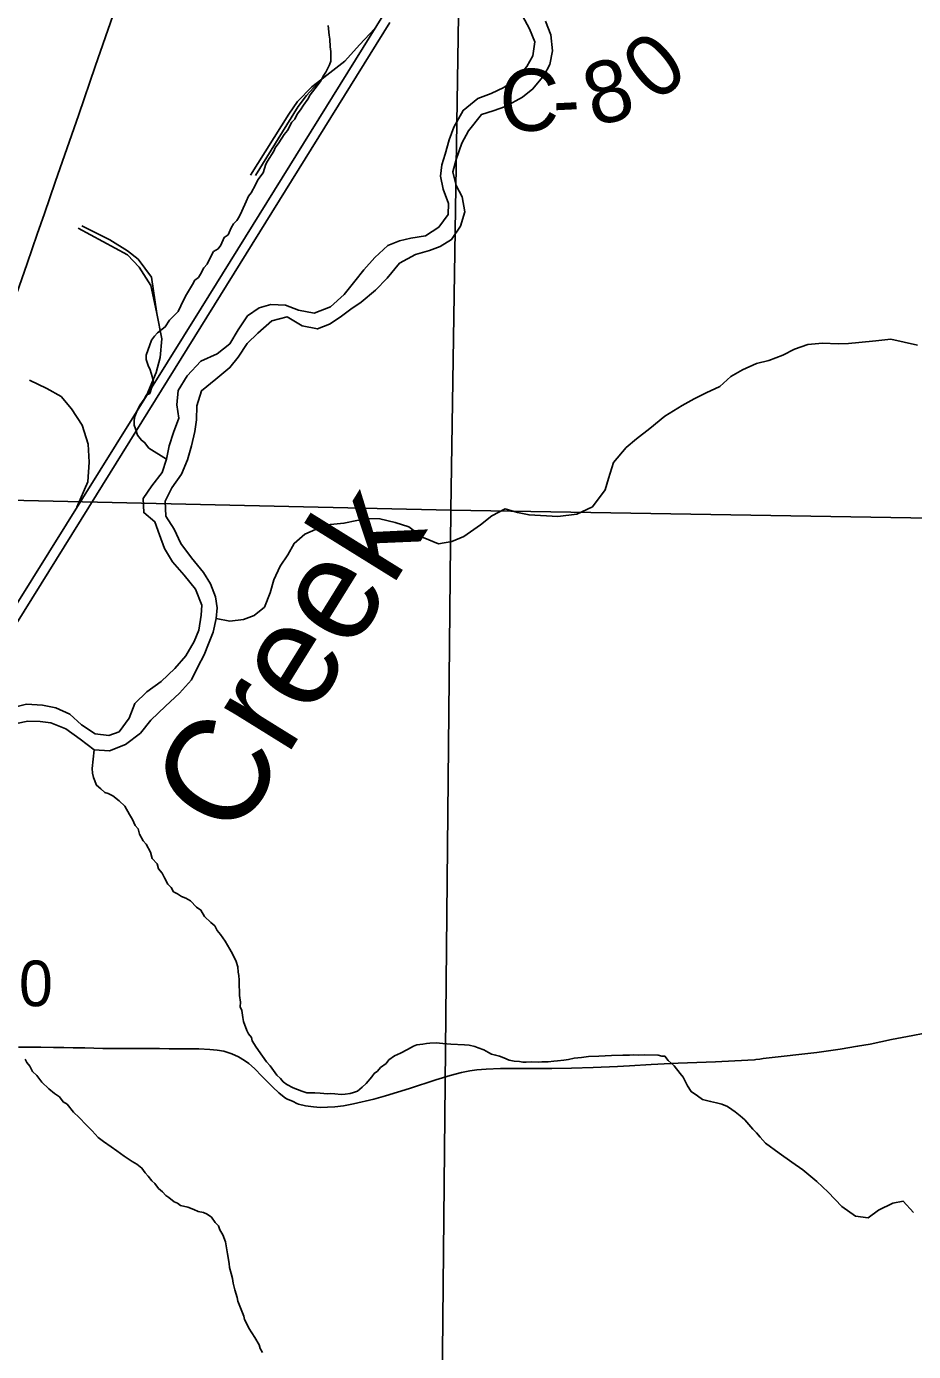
# Model space of a CAD drawing. Extents: x -8.8 to 41.4, y 0 to 34.6.
# Drawn here: x 2.947 to 3.761, y 16.815 to 18.031 of the extents above; entities that cross this region are included whole.
import ezdxf

# ---------------------------------------------------------------- set-up
doc = ezdxf.new("R2010")
doc.units = 0
for name, color, linetype in [('GM_X_City_Street', 7, 'Continuous'), ('GM_X_Corporation', 7, 'Continuous'), ('GM_X_Corporation_Text', 7, 'Continuous'), ('GM_X_Major_Lake', 7, 'Continuous'), ('GM_X_Minor_River', 7, 'Continuous'), ('GM_X_Rail_Line', 7, 'Continuous'), ('GM_X_State_Route', 7, 'Continuous'), ('GM_X_Township_Road_Text', 7, 'Continuous'), ('GM_X_Township_Text', 7, 'Continuous')]:
    doc.layers.add(name, color=color, linetype=linetype)

msp = doc.modelspace()

# ---------------------------------------------------------------- linework, layer by layer
at = {"layer": 'GM_X_City_Street'}
msp.add_lwpolyline([(2.9329, 17.7709), (2.9474, 17.8132), (2.9568, 17.8402), (2.9634, 17.859), (2.9733, 17.8877), (2.9949, 17.95), (3.0099, 17.9941), (3.0265, 18.0415)], dxfattribs=at)
at = {"layer": 'GM_X_Corporation'}
for points in [[(2.3634, 18.686), (3.3405, 18.6729), (3.3534, 18.6726), (3.3365, 17.5869), (2.3759, 17.6086)], [(3.3534, 18.6726), (4.3593, 18.6581), (4.3706, 18.6579), (4.3651, 17.5696), (3.3365, 17.5869)], [(2.3759, 17.6086), (3.3365, 17.5869), (3.3269, 16.5968), (2.3543, 16.6037)], [(3.3365, 17.5869), (4.3651, 17.5696), (4.3404, 16.586), (3.3269, 16.5968)]]:
    msp.add_lwpolyline(points, close=True, dxfattribs=at)
msp.add_lwpolyline([(2.55, 16.7797), (2.5844, 16.8441), (2.5865, 16.8494), (2.5874, 16.8538), (2.5949, 16.9318), (2.6264, 16.9827), (2.7854, 17.1797), (2.7946, 17.191), (2.7568, 17.1927), (2.7774, 17.2258), (2.8568, 17.3532), (3.0111, 17.601), (3.2806, 18.0343)], dxfattribs=at)
at = {"layer": 'GM_X_Major_Lake'}
for points in [[(3.1015, 17.659), (3.103, 17.6696), (3.1034, 17.6825), (3.1076, 17.6964), (3.1208, 17.707), (3.1337, 17.7177), (3.1412, 17.7273), (3.1495, 17.7396), (3.1593, 17.7491), (3.1722, 17.7605), (3.1863, 17.7643), (3.2001, 17.7559), (3.214, 17.7531), (3.2252, 17.7574), (3.2348, 17.7639), (3.2446, 17.7712), (3.2542, 17.7777), (3.2675, 17.7887), (3.278, 17.7998), (3.2895, 17.8135), (3.3041, 17.8214), (3.3171, 17.8252), (3.3267, 17.8287), (3.3372, 17.8352), (3.3455, 17.8474), (3.3493, 17.8606), (3.3471, 17.8744), (3.3414, 17.8848), (3.3383, 17.8974), (3.3413, 17.9087), (3.3467, 17.9237), (3.3528, 17.9349), (3.3646, 17.9498), (3.3753, 17.9532), (3.3868, 17.9574), (3.4023, 17.9657), (3.412, 17.9734), (3.4222, 17.986), (3.4275, 17.9957), (3.4298, 18.0085), (3.4283, 18.023), (3.4234, 18.0357)], [(3.4023, 18.0405), (3.4087, 18.0285), (3.4137, 18.0166), (3.4118, 18.0037), (3.4062, 17.994), (3.3967, 17.9829), (3.3851, 17.9746), (3.3735, 17.9692), (3.3613, 17.9647), (3.348, 17.9537), (3.3392, 17.9384), (3.3351, 17.9268), (3.3312, 17.9136), (3.3283, 17.9038), (3.3272, 17.8932), (3.3295, 17.8814), (3.3344, 17.8683), (3.3341, 17.858), (3.3254, 17.8465), (3.3134, 17.8386), (3.2997, 17.8363), (3.2893, 17.834), (3.2786, 17.8298), (3.2669, 17.8187), (3.2567, 17.8073), (3.2484, 17.7969), (3.2385, 17.7847), (3.226, 17.7733), (3.2111, 17.7677), (3.1967, 17.7704), (3.1847, 17.7749), (3.1711, 17.7754), (3.1604, 17.7726), (3.1499, 17.765), (3.1412, 17.7524), (3.1336, 17.7393)], [(3.1336, 17.7393), (3.1219, 17.7302), (3.1069, 17.7234), (3.0944, 17.7101), (3.086, 17.6967), (3.0848, 17.6835), (3.0867, 17.6713), (3.0818, 17.6581), (3.078, 17.6457), (3.0753, 17.6336), (3.0715, 17.6212), (3.062, 17.609), (3.0541, 17.5975), (3.0545, 17.5845), (3.0648, 17.5762), (3.069, 17.564), (3.0736, 17.5517), (3.0808, 17.5393), (3.0918, 17.5272), (3.102, 17.5143), (3.108, 17.4997), (3.1073, 17.4903), (3.105, 17.4767), (3.1009, 17.4661), (3.0933, 17.4531), (3.0831, 17.4416), (3.0705, 17.4295), (3.0574, 17.42), (3.0464, 17.4093), (3.0411, 17.3958), (3.0319, 17.3832), (3.0224, 17.3801), (3.0099, 17.3816), (2.9973, 17.3896), (2.9866, 17.3994), (2.9738, 17.4055), (2.9614, 17.4078), (2.947, 17.4086), (2.9218, 17.4026)], [(2.9378, 17.3911), (2.9481, 17.393), (2.9594, 17.3927), (2.9692, 17.3916), (2.9831, 17.3862), (2.9961, 17.3767), (3.0091, 17.3668), (3.0231, 17.366), (3.0377, 17.3716), (3.0516, 17.3822), (3.0611, 17.3941), (3.0744, 17.407), (3.0873, 17.4187), (3.0983, 17.4309), (3.1043, 17.4429), (3.11, 17.4541), (3.1141, 17.4642), (3.1182, 17.4747), (3.1209, 17.4872), (3.1219, 17.497), (3.1204, 17.5073), (3.1158, 17.5192), (3.1093, 17.5297), (3.0983, 17.5429), (3.0885, 17.5561), (3.0824, 17.5692), (3.0748, 17.5812), (3.0741, 17.5949), (3.0802, 17.6073), (3.0893, 17.6199), (3.0947, 17.633), (3.0985, 17.6458), (3.1015, 17.659)]]:
    msp.add_lwpolyline(points, dxfattribs=at)
at = {"layer": 'GM_X_Minor_River'}
for points in [[(3.0753, 17.6336), (3.0593, 17.6438), (3.0553, 17.6489), (3.0524, 17.6509), (3.0487, 17.6556), (3.047, 17.6614), (3.0456, 17.6648), (3.0458, 17.6694), (3.0463, 17.6728), (3.0475, 17.6758), (3.0492, 17.6795), (3.0512, 17.6836), (3.0549, 17.6888), (3.0569, 17.6922), (3.06, 17.694), (3.0621, 17.6996), (3.0634, 17.7041), (3.0624, 17.7095), (3.0604, 17.7156), (3.0586, 17.7195), (3.0569, 17.7252), (3.0567, 17.729), (3.0617, 17.7429), (3.0645, 17.7466), (3.0673, 17.7496), (3.0743, 17.755), (3.0783, 17.7613), (3.0826, 17.7654), (3.0862, 17.769), (3.0887, 17.7743), (3.0928, 17.7832), (3.0948, 17.7862), (3.0992, 17.794), (3.1013, 17.7978), (3.1048, 17.8003), (3.1068, 17.8033), (3.1097, 17.8092), (3.1128, 17.8126), (3.1161, 17.8197), (3.1186, 17.8241), (3.1228, 17.8266), (3.1252, 17.83), (3.1285, 17.8371), (3.132, 17.8396), (3.1349, 17.846), (3.137, 17.8497), (3.1401, 17.8526), (3.1421, 17.856), (3.1446, 17.8612), (3.1487, 17.8702), (3.1508, 17.8751), (3.1532, 17.878), (3.1572, 17.8855), (3.1593, 17.89), (3.1641, 17.8963), (3.1666, 17.9042), (3.1683, 17.9071), (3.1739, 17.9164), (3.1752, 17.9194), (3.1787, 17.9239), (3.1836, 17.9317), (3.1864, 17.9354), (3.1904, 17.9428), (3.1932, 17.9458), (3.1953, 17.9503), (3.1984, 17.9543), (3.2012, 17.9584), (3.2052, 17.964), (3.2073, 17.9681), (3.2137, 17.9762), (3.2172, 17.9807), (3.2193, 17.9851), (3.2217, 17.9889), (3.225, 17.9956), (3.2263, 17.999), (3.2264, 18.002), (3.2262, 18.0077), (3.2256, 18.0119), (3.2254, 18.0191), (3.2248, 18.0226), (3.224, 18.0317)], [(3.1209, 17.4872), (3.1336, 17.4848), (3.1462, 17.4864), (3.1558, 17.49), (3.1654, 17.4977), (3.1707, 17.5108), (3.174, 17.5229), (3.1797, 17.5353), (3.1867, 17.5457), (3.1927, 17.5562), (3.2024, 17.5647), (3.2124, 17.569), (3.2261, 17.5736), (3.2383, 17.5748), (3.2501, 17.5772), (3.2612, 17.5792), (3.2714, 17.5789), (3.2853, 17.5755), (3.2981, 17.5714), (3.3112, 17.5616), (3.3251, 17.556), (3.3376, 17.558), (3.3484, 17.5626), (3.3638, 17.5732), (3.3742, 17.5817), (3.3865, 17.5879), (3.3978, 17.5845), (3.4084, 17.5824), (3.4349, 17.581), (3.4524, 17.5832), (3.4666, 17.5897), (3.4784, 17.6053), (3.4813, 17.6159), (3.4858, 17.6306), (3.4976, 17.6443), (3.5072, 17.6524), (3.5192, 17.6616), (3.5332, 17.673), (3.549, 17.6829), (3.5601, 17.689), (3.5709, 17.6945), (3.5835, 17.7002), (3.5936, 17.7095), (3.6044, 17.7156), (3.6174, 17.7214), (3.6285, 17.7241), (3.6415, 17.7291), (3.6523, 17.7346), (3.6645, 17.7388), (3.6778, 17.74), (3.6922, 17.7393), (3.7017, 17.7398), (3.7112, 17.7407), (3.7268, 17.7422), (3.7405, 17.7438), (3.765, 17.7383)], [(3.0091, 17.3668), (3.0071, 17.3497), (3.0074, 17.3455), (3.0084, 17.3413), (3.0112, 17.3343), (3.0152, 17.3311), (3.0189, 17.3276), (3.0219, 17.3267), (3.026, 17.3247), (3.032, 17.3199), (3.0371, 17.3152), (3.0414, 17.3074), (3.0443, 17.3028), (3.0468, 17.2974), (3.0493, 17.2942), (3.0506, 17.2893), (3.0539, 17.2834), (3.0568, 17.2803), (3.0607, 17.2729), (3.0624, 17.2672), (3.0668, 17.2621), (3.0682, 17.2575), (3.0714, 17.2536), (3.0736, 17.2493), (3.0768, 17.2435), (3.0797, 17.2404), (3.0819, 17.2365), (3.0856, 17.2345), (3.0893, 17.2321), (3.0931, 17.2308), (3.0976, 17.2283), (3.103, 17.2225), (3.1071, 17.2197), (3.1104, 17.2138), (3.1162, 17.2083), (3.1199, 17.2052), (3.1221, 17.2009), (3.125, 17.1974), (3.1293, 17.1911), (3.1336, 17.1838), (3.1361, 17.1795), (3.1393, 17.1726), (3.141, 17.1676), (3.1412, 17.1626), (3.1419, 17.1596), (3.1421, 17.1554), (3.1423, 17.1504), (3.1425, 17.1451), (3.1424, 17.1413), (3.1433, 17.1352), (3.1432, 17.131), (3.1446, 17.1275), (3.1455, 17.1211), (3.1461, 17.1176), (3.1492, 17.1091), (3.1507, 17.1061), (3.1536, 17.1029), (3.1542, 17.0998), (3.1578, 17.094), (3.1636, 17.0855), (3.1672, 17.0804), (3.1705, 17.0769), (3.1738, 17.0726), (3.1767, 17.0683), (3.18, 17.0651), (3.1826, 17.062), (3.1859, 17.0596), (3.1919, 17.0567), (3.1998, 17.0534), (3.2043, 17.0521), (3.2115, 17.0519), (3.2164, 17.0517), (3.2232, 17.0511), (3.2263, 17.0514), (3.2301, 17.0512), (3.2358, 17.0506), (3.2396, 17.0509), (3.2442, 17.0515), (3.2472, 17.0522), (3.2507, 17.0535), (3.255, 17.0572), (3.2589, 17.0605), (3.2641, 17.0668), (3.2661, 17.0697), (3.2692, 17.0719), (3.272, 17.0752), (3.2771, 17.0788), (3.2795, 17.0822), (3.2849, 17.0858), (3.2903, 17.0883), (3.2966, 17.0918), (3.3024, 17.0947), (3.3054, 17.0961), (3.3108, 17.0967), (3.3142, 17.0973), (3.3173, 17.0976), (3.323, 17.0978), (3.3291, 17.0972), (3.3366, 17.0965)], [(3.3366, 17.0965), (3.3492, 17.0961), (3.3533, 17.0956), (3.3586, 17.0946), (3.3616, 17.0934), (3.3669, 17.0913), (3.371, 17.0889), (3.374, 17.0876), (3.3777, 17.0867), (3.3811, 17.0855), (3.3853, 17.0842), (3.3901, 17.0821), (3.3947, 17.0812), (3.3996, 17.0807), (3.4026, 17.0802), (3.4057, 17.0801), (3.4102, 17.0803), (3.4167, 17.0801), (3.4201, 17.0803), (3.4258, 17.0805), (3.4312, 17.0811), (3.4346, 17.0813), (3.4403, 17.0819), (3.4445, 17.0825), (3.4499, 17.0838), (3.4564, 17.0844), (3.4629, 17.0853), (3.4724, 17.0857), (3.4842, 17.0864), (3.4945, 17.0865), (3.5006, 17.0866), (3.5044, 17.0869), (3.5086, 17.0867), (3.5143, 17.0869), (3.5268, 17.0865), (3.5302, 17.0856), (3.5332, 17.0855), (3.5361, 17.0816), (3.5417, 17.0768), (3.5471, 17.0698), (3.55, 17.0663), (3.5525, 17.0616), (3.554, 17.0585), (3.5572, 17.0531), (3.5631, 17.0491), (3.5676, 17.0459), (3.5713, 17.045), (3.5751, 17.0441), (3.5804, 17.0428), (3.5853, 17.0415), (3.5905, 17.0394), (3.5946, 17.0366), (3.5976, 17.0346), (3.6024, 17.031), (3.6065, 17.0271), (3.6138, 17.0185), (3.6171, 17.0153), (3.6207, 17.0114)], [(2.9456, 17.0828), (2.9471, 17.0797), (2.95, 17.0766), (2.9525, 17.0716), (2.9562, 17.068), (2.9609, 17.0618), (2.9675, 17.0558), (2.9727, 17.0515), (2.9771, 17.0483), (2.9804, 17.0436), (2.9841, 17.0416), (2.9899, 17.0341), (2.9951, 17.0294), (3.0017, 17.0227), (3.0072, 17.0172), (3.0127, 17.0109), (3.0175, 17.0074), (3.0246, 17.0025), (3.0298, 16.9989), (3.0364, 16.9938), (3.0439, 16.989), (3.0483, 16.9865), (3.0528, 16.9829), (3.0557, 16.9787), (3.0586, 16.9755), (3.0619, 16.9712), (3.0648, 16.9688), (3.0681, 16.9642), (3.0718, 16.961), (3.0747, 16.9579), (3.0777, 16.9559), (3.0825, 16.9519), (3.0855, 16.9506), (3.0884, 16.9486), (3.0949, 16.9469), (3.1005, 16.9448), (3.1046, 16.9431), (3.1095, 16.9422), (3.1129, 16.9406), (3.1166, 16.9378), (3.1202, 16.9331), (3.1232, 16.93), (3.1245, 16.9261), (3.1271, 16.9218), (3.1295, 16.9153), (3.1304, 16.9096), (3.1314, 16.9042), (3.133, 16.8954), (3.1332, 16.8916), (3.1349, 16.8862), (3.1359, 16.8816), (3.1365, 16.8774), (3.1382, 16.8713), (3.1402, 16.864), (3.1409, 16.8609), (3.1433, 16.8548), (3.1465, 16.8471), (3.1471, 16.844), (3.1493, 16.8401), (3.151, 16.8359), (3.1539, 16.8316), (3.1564, 16.8273), (3.1604, 16.8208), (3.1614, 16.8173), (3.1635, 16.8138)], [(3.6207, 17.0114), (3.6254, 17.0059), (3.6381, 16.9965), (3.6496, 16.9883), (3.6597, 16.9812), (3.6727, 16.9706), (3.6831, 16.9609), (3.6957, 16.9477), (3.7083, 16.9387), (3.7197, 16.9372), (3.7293, 16.9442), (3.7424, 16.9507), (3.7519, 16.9524), (3.7615, 16.9423)]]:
    msp.add_lwpolyline(points, dxfattribs=at)
at = {"layer": 'GM_X_Rail_Line'}
for points in [[(2.5712, 16.904), (2.5981, 16.9546), (2.7961, 17.2741), (3.1073, 17.7722), (3.3429, 18.1516), (3.398, 18.2398), (3.4347, 18.2917)], [(3.2667, 18.0289), (3.2528, 18.0138), (3.2393, 17.9988), (3.2226, 17.9861), (3.2168, 17.9815)], [(3.2168, 17.9815), (3.2089, 17.9752), (3.1957, 17.9618), (3.1879, 17.9501), (3.1525, 17.8942)], [(3.1571, 17.8938), (3.1963, 17.9573), (3.2041, 17.9674), (3.2168, 17.9815)], [(3.0664, 17.7674), (3.0609, 17.7931), (3.0504, 17.8098), (3.0397, 17.8211), (2.9943, 17.8455)], [(3.0664, 17.7674), (3.0615, 17.8007), (3.0494, 17.8172), (3.0397, 17.8248), (3.0233, 17.835), (2.9976, 17.8478)], [(3.0575, 17.6925), (3.066, 17.7132), (3.0695, 17.727), (3.071, 17.744), (3.0664, 17.7674)], [(2.9931, 17.5895), (3.0031, 17.6129), (3.0044, 17.6308), (3.0036, 17.6474), (2.998, 17.6649), (2.9883, 17.6799), (2.9787, 17.691), (2.9655, 17.6986), (2.9497, 17.706)]]:
    msp.add_lwpolyline(points, dxfattribs=at)
at = {"layer": 'GM_X_State_Route'}
msp.add_lwpolyline([(2.9396, 17.0939), (2.9483, 17.0939), (2.9545, 17.0938), (2.9601, 17.0938), (2.9718, 17.0936), (2.9811, 17.0935), (2.9898, 17.0934), (3.0004, 17.0932), (3.0171, 17.0928), (3.0283, 17.0927), (3.0419, 17.0927), (3.0605, 17.0927), (3.0691, 17.0926), (3.0778, 17.0925), (3.0852, 17.0924), (3.1051, 17.0923), (3.1151, 17.0918), (3.1219, 17.0912), (3.1281, 17.0901), (3.1354, 17.0879), (3.1417, 17.085), (3.1471, 17.0818), (3.1511, 17.0788), (3.1563, 17.0742), (3.1634, 17.0671), (3.173, 17.0571), (3.1785, 17.0521), (3.1836, 17.048), (3.1856, 17.0466), (3.1895, 17.0449), (3.1918, 17.044), (3.195, 17.0423), (3.1967, 17.0416), (3.2032, 17.0401), (3.2104, 17.039), (3.2166, 17.0386), (3.2233, 17.0387), (3.2301, 17.0392), (3.2381, 17.0401), (3.2472, 17.0419), (3.2659, 17.0462), (3.2766, 17.0492), (3.2986, 17.0559), (3.3228, 17.0638), (3.3359, 17.0678), (3.3462, 17.0705), (3.3541, 17.0722), (3.3603, 17.073), (3.3691, 17.0737), (3.3821, 17.0742), (3.4107, 17.0744), (3.4294, 17.0744), (3.4474, 17.0747), (3.4672, 17.0752), (3.4895, 17.0761), (3.5007, 17.0768), (3.5206, 17.078), (3.5385, 17.0788), (3.5454, 17.0793), (3.5795, 17.0805), (3.6093, 17.0819), (3.6155, 17.0824), (3.6167, 17.0826), (3.6204, 17.083), (3.6235, 17.0834), (3.6426, 17.0855), (3.6561, 17.0872), (3.6727, 17.0891), (3.6942, 17.0921), (3.7101, 17.0947), (3.7217, 17.0967), (3.7411, 17.1008), (3.7607, 17.1045), (3.7704, 17.1063)], dxfattribs=at)

# ---------------------------------------------------------------- texts
at = {"layer": 'GM_X_Corporation_Text'}
msp.add_text('Creek', height=0.09467, rotation=58.1724, dxfattribs=at).set_placement((3.1374, 17.2821))
at = {"layer": 'GM_X_Township_Road_Text'}
for s, rotation, p in [('0', 39.5005, (3.5246, 17.9596)), ('8', 15.5424, (3.468, 17.9383)), ('C', 359.5999, (3.381, 17.9352)), ('-', 2.7735, (3.4311, 17.935))]:
    msp.add_text(s, height=0.0568, rotation=rotation, dxfattribs=at).set_placement(p)
at = {"layer": 'GM_X_Township_Text'}
msp.add_text('10', height=0.04186, rotation=0, dxfattribs=at).set_placement((2.9088, 17.1315))

doc.saveas('drawing.dxf')
